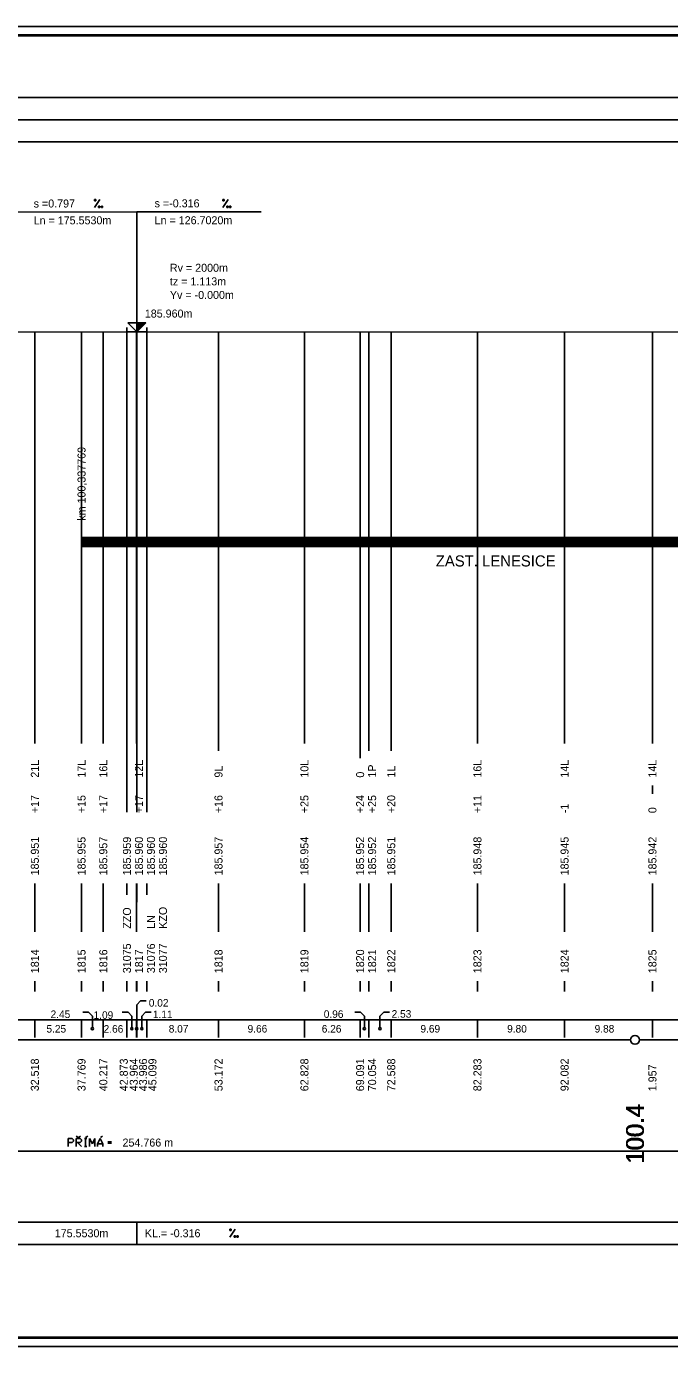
# Model space of a CAD drawing. Extents: x 0 to 10087, y -805 to 297.
# Drawn here: x 8043.1 to 8187.8, y 0 to 297 of the extents above; entities that cross this region are included whole.
import ezdxf

# ---------------------------------------------------------------- set-up
doc = ezdxf.new("R2010")
doc.units = 0
for name, color, linetype in [('CARKY_HODNOT', 7, 'Continuous'), ('KRIV1_CARA', 7, 'Continuous'), ('KRIV1_TEXT', 7, 'Continuous'), ('L_OBJEKTY_TEXT', 7, 'Continuous'), ('L_OBJEKTY_TVAR', 7, 'Continuous'), ('NIVELETA_CARA', 7, 'Continuous'), ('NIVELETA_TEXT', 7, 'Continuous'), ('RAM', 7, 'Continuous'), ('REZERVA', 7, 'Continuous'), ('STAN_CARA', 7, 'Continuous'), ('STAN_PAS', 7, 'Continuous'), ('STAN_TEXT', 7, 'Continuous'), ('TEXT', 7, 'Continuous'), ('TXT_C_BODU', 7, 'Continuous')]:
    doc.layers.add(name, color=color, linetype=linetype)

msp = doc.modelspace()

# ---------------------------------------------------------------- linework, layer by layer
at = {"layer": 'CARKY_HODNOT'}
for p, q in [((8045.04, 138.35), (8045.04, 228.25)), ((8055.54, 138.35), (8055.54, 228.28)), ((8060.43, 138.35), (8060.43, 228.29)), ((8065.75, 138.35), (8065.75, 228.3)), ((8067.93, 138.35), (8067.93, 228.3)), ((8067.97, 138.35), (8067.97, 228.3)), ((8070.2, 138.35), (8070.2, 228.3)), ((8086.34, 138.35), (8086.34, 228.29)), ((8105.66, 138.35), (8105.66, 228.27)), ((8118.18, 138.35), (8118.18, 228.26)), ((8120.11, 138.35), (8120.11, 228.26)), ((8125.18, 138.35), (8125.18, 228.25)), ((8144.57, 138.35), (8144.57, 228.24)), ((8164.16, 138.35), (8164.16, 228.22)), ((8183.91, 138.35), (8183.91, 228.21)), ((8045.04, 135.65), (8045.04, 138.35)), ((8055.54, 135.65), (8055.54, 138.35)), ((8060.43, 135.65), (8060.43, 138.35)), ((8065.75, 126.2), (8065.75, 138.35)), ((8067.93, 135.65), (8067.93, 138.35)), ((8067.97, 126.2), (8067.97, 138.35)), ((8070.2, 126.2), (8070.2, 138.35)), ((8086.34, 134), (8086.34, 138.35)), ((8105.66, 135.65), (8105.66, 138.35)), ((8118.18, 132.35), (8118.18, 138.35)), ((8120.11, 134), (8120.11, 138.35)), ((8125.18, 134), (8125.18, 138.35)), ((8144.57, 135.65), (8144.57, 138.35)), ((8164.16, 135.65), (8164.16, 138.35)), ((8183.91, 135.65), (8183.91, 138.35)), ((8065.75, 120.25), (8065.75, 126.2)), ((8067.97, 120.25), (8067.97, 126.2)), ((8070.2, 120.25), (8070.2, 126.2)), ((8183.91, 124.35), (8183.91, 126.2)), ((8045.04, 93.3), (8045.04, 104.2)), ((8055.54, 93.3), (8055.54, 104.2)), ((8060.43, 93.3), (8060.43, 104.2)), ((8065.75, 101.65), (8065.75, 104.2)), ((8067.93, 93.3), (8067.93, 104.2)), ((8067.97, 100), (8067.97, 104.2)), ((8070.2, 101.65), (8070.2, 104.2)), ((8086.34, 93.3), (8086.34, 104.2)), ((8105.66, 93.3), (8105.66, 104.2)), ((8118.18, 93.3), (8118.18, 104.2)), ((8120.11, 93.3), (8120.11, 104.2)), ((8125.18, 93.3), (8125.18, 104.2)), ((8144.57, 93.3), (8144.57, 104.2)), ((8164.16, 93.3), (8164.16, 104.2)), ((8183.91, 93.3), (8183.91, 104.2)), ((8045.04, 79.9), (8045.04, 82.2)), ((8055.54, 79.9), (8055.54, 82.2)), ((8060.43, 79.9), (8060.43, 82.2)), ((8065.75, 79.9), (8065.75, 82.2)), ((8067.93, 79.9), (8067.93, 82.2)), ((8067.97, 79.9), (8067.97, 82.2)), ((8070.2, 79.9), (8070.2, 82.2)), ((8086.34, 79.9), (8086.34, 82.2)), ((8105.66, 79.9), (8105.66, 82.2)), ((8118.18, 79.9), (8118.18, 82.2)), ((8120.11, 79.9), (8120.11, 82.2)), ((8125.18, 79.9), (8125.18, 82.2)), ((8144.57, 79.9), (8144.57, 82.2)), ((8164.16, 79.9), (8164.16, 82.2)), ((8183.91, 79.9), (8183.91, 82.2))]:
    msp.add_line(p, q, dxfattribs=at)
at = {"layer": 'KRIV1_CARA'}
msp.add_line((7811.8, 44), (8321.33, 44), dxfattribs=at)
at = {"layer": 'KRIV1_TEXT'}
for p, q in [((8052.54, 45), (8052.54, 46.8)), ((8052.54, 46.8), (8053.46, 46.8)), ((8053.44, 45.9), (8052.54, 45.9)), ((8053.76, 46.2), (8053.44, 45.9)), ((8053.46, 46.8), (8053.76, 46.49)), ((8053.76, 46.49), (8053.76, 46.2)), ((8054.83, 47.03), (8054.32, 47.37)), ((8054.34, 45), (8054.34, 46.8)), ((8054.34, 46.8), (8055.24, 46.8)), ((8055.24, 45.9), (8054.34, 45.9)), ((8054.64, 45.9), (8055.54, 45)), ((8054.83, 47.03), (8055.34, 47.37)), ((8055.24, 46.8), (8055.54, 46.51)), ((8055.54, 46.2), (8055.24, 45.9)), ((8055.54, 46.51), (8055.54, 46.2)), ((8056.18, 46.79), (8056.75, 46.79)), ((8056.18, 45), (8056.75, 45)), ((8056.46, 47.03), (8056.97, 47.37)), ((8056.46, 45), (8056.46, 46.79)), ((8057.35, 45), (8057.35, 46.79)), ((8057.35, 46.79), (8057.97, 45.6)), ((8057.97, 45.6), (8058.55, 46.79)), ((8058.55, 46.79), (8058.55, 45)), ((8059.75, 46.81), (8059.15, 45.6)), ((8059.15, 45), (8059.15, 45.6)), ((8059.15, 45.6), (8060.35, 45.6)), ((8060.35, 45.6), (8059.75, 46.81)), ((8059.77, 47.03), (8060.28, 47.37)), ((8060.35, 45.6), (8060.35, 45)), ((8061.47, 46.07), (8062.28, 46.07)), ((8061.47, 45.75), (8062.28, 45.75))]:
    msp.add_line(p, q, dxfattribs=at)
at = {"layer": 'L_OBJEKTY_TVAR'}
for p, q in [((8055.54, 180), (8055.54, 183)), ((8055.54, 182), (8246.96, 182)), ((8055.54, 181.9), (8246.96, 181.9)), ((8055.54, 181.8), (8246.96, 181.8)), ((8055.54, 181.7), (8246.96, 181.7)), ((8055.54, 181.6), (8246.96, 181.6)), ((8055.54, 181.5), (8246.96, 181.5)), ((8055.54, 181.4), (8246.96, 181.4)), ((8055.54, 181.3), (8246.96, 181.3)), ((8055.54, 181.2), (8246.96, 181.2)), ((8055.54, 181.1), (8246.96, 181.1)), ((8055.54, 181), (8246.96, 181)), ((8055.54, 180.9), (8246.96, 180.9)), ((8055.54, 180.8), (8246.96, 180.8)), ((8055.54, 180.7), (8246.96, 180.7)), ((8055.54, 180.6), (8246.96, 180.6)), ((8055.54, 180.5), (8246.96, 180.5)), ((8055.54, 180.4), (8246.96, 180.4)), ((8055.54, 180.3), (8246.96, 180.3)), ((8055.54, 180.2), (8246.96, 180.2)), ((8055.54, 180.1), (8246.96, 180.1)), ((8055.54, 180), (8246.96, 180))]:
    msp.add_line(p, q, dxfattribs=at)
at = {"layer": 'NIVELETA_CARA'}
for p, q in [((300, 281), (8321.33, 281)), ((300, 276), (8321.33, 276)), ((300, 271), (8321.33, 271)), ((8067.97, 255.3), (8039.97, 255.24)), ((8067.97, 228.3), (8067.97, 255.3)), ((8067.97, 255.3), (8095.97, 255.28)), ((8065.75, 228.3), (8065.75, 229.3)), ((8067.97, 228.3), (8065.97, 230.3)), ((8065.97, 230.3), (8069.97, 230.3)), ((8067.97, 228.3), (8067.97, 230.3)), ((8069.97, 230.3), (8067.97, 228.3)), ((8068.04, 228.37), (8068.04, 230.3)), ((8068.11, 228.43), (8068.11, 230.3)), ((8068.17, 228.5), (8068.17, 230.3)), ((8068.24, 228.57), (8068.24, 230.3)), ((8068.31, 228.63), (8068.31, 230.3)), ((8068.37, 228.7), (8068.37, 230.3)), ((8068.44, 228.77), (8068.44, 230.3)), ((8068.51, 228.83), (8068.51, 230.3)), ((8068.57, 228.9), (8068.57, 230.3)), ((8068.64, 228.97), (8068.64, 230.3)), ((8068.71, 229.03), (8068.71, 230.3)), ((8068.77, 229.1), (8068.77, 230.3)), ((8068.84, 229.17), (8068.84, 230.3)), ((8068.91, 229.23), (8068.91, 230.3)), ((8068.97, 229.3), (8068.97, 230.3)), ((8069.04, 229.37), (8069.04, 230.3)), ((8069.11, 229.43), (8069.11, 230.3)), ((8069.17, 229.5), (8069.17, 230.3)), ((8069.24, 229.57), (8069.24, 230.3)), ((8069.31, 229.63), (8069.31, 230.3)), ((8069.37, 229.7), (8069.37, 230.3)), ((8069.44, 229.77), (8069.44, 230.3)), ((8069.51, 229.83), (8069.51, 230.3)), ((8069.57, 229.9), (8069.57, 230.3)), ((8069.64, 229.97), (8069.64, 230.3)), ((8069.71, 230.03), (8069.71, 230.3)), ((8069.77, 230.1), (8069.77, 230.3)), ((8069.84, 230.17), (8069.84, 230.3)), ((8069.91, 230.23), (8069.91, 230.3)), ((8070.2, 228.3), (8070.2, 229.3)), ((7721.21, 227.61), (8065.75, 228.3)), ((8065.75, 228.3), (8067.97, 228.3)), ((8065.75, 228.3), (8066.25, 228.3)), ((8066.25, 228.3), (8066.75, 228.3)), ((8066.75, 228.3), (8067.25, 228.3)), ((8067.25, 228.3), (8067.75, 228.3)), ((8067.75, 228.3), (8067.97, 228.3)), ((8067.97, 228.3), (8070.2, 228.3)), ((8067.97, 228.3), (8068.47, 228.3)), ((8068.47, 228.3), (8068.97, 228.3)), ((8068.97, 228.3), (8069.47, 228.3)), ((8069.47, 228.3), (8069.97, 228.3)), ((8069.97, 228.3), (8070.2, 228.3)), ((8070.2, 228.3), (8321.38, 228.1)), ((500, 28), (8321.33, 28)), ((8067.97, 23), (8067.97, 28)), ((500, 23), (8321.33, 23))]:
    msp.add_line(p, q, dxfattribs=at)
at = {"layer": 'NIVELETA_TEXT'}
for p, q in [((8058.47, 256.28), (8059.66, 258.08)), ((8058.47, 258.08), (8058.47, 257.78)), ((8058.48, 258.08), (8058.47, 258.07)), ((8058.47, 257.78), (8058.77, 257.78)), ((8058.77, 258.08), (8058.48, 258.08)), ((8058.77, 257.78), (8058.77, 258.08)), ((8059.38, 256.58), (8059.38, 256.29)), ((8059.39, 256.58), (8059.38, 256.58)), ((8059.38, 256.29), (8059.68, 256.29)), ((8059.68, 256.58), (8059.39, 256.58)), ((8059.68, 256.29), (8059.68, 256.58)), ((8060, 256.58), (8060, 256.29)), ((8060.29, 256.58), (8060, 256.58)), ((8060, 256.58), (8060, 256.58)), ((8060, 256.29), (8060.29, 256.29)), ((8060.29, 256.29), (8060.29, 256.58)), ((8087.32, 256.29), (8088.51, 258.08)), ((8087.33, 258.08), (8087.33, 257.78)), ((8087.62, 258.08), (8087.33, 258.08)), ((8087.33, 258.08), (8087.33, 258.08)), ((8087.33, 257.78), (8087.62, 257.78)), ((8087.62, 257.78), (8087.62, 258.08)), ((8088.23, 256.58), (8088.23, 256.29)), ((8088.24, 256.58), (8088.23, 256.58)), ((8088.23, 256.29), (8088.53, 256.29)), ((8088.53, 256.58), (8088.24, 256.58)), ((8088.53, 256.29), (8088.53, 256.58)), ((8088.85, 256.58), (8088.85, 256.29)), ((8089.14, 256.58), (8088.85, 256.58)), ((8088.85, 256.58), (8088.85, 256.58)), ((8088.85, 256.29), (8089.14, 256.29)), ((8089.14, 256.29), (8089.14, 256.58)), ((8088.92, 24.6), (8090.11, 26.4)), ((8088.92, 26.4), (8088.92, 26.1)), ((8088.93, 26.4), (8088.92, 26.39)), ((8088.92, 26.1), (8089.22, 26.1)), ((8089.22, 26.4), (8088.93, 26.4)), ((8089.22, 26.1), (8089.22, 26.4)), ((8089.83, 24.9), (8089.83, 24.6)), ((8089.84, 24.9), (8089.83, 24.89)), ((8089.83, 24.6), (8090.13, 24.6)), ((8090.13, 24.9), (8089.84, 24.9)), ((8090.13, 24.6), (8090.13, 24.9)), ((8090.45, 24.9), (8090.45, 24.6)), ((8090.74, 24.9), (8090.45, 24.9)), ((8090.45, 24.9), (8090.45, 24.89)), ((8090.45, 24.6), (8090.74, 24.6)), ((8090.74, 24.6), (8090.74, 24.9))]:
    msp.add_line(p, q, dxfattribs=at)
at = {"layer": 'RAM'}
for p, q in [((8636.33, 297), (0, 297)), ((8634.33, 295.1), (2, 295.1)), ((8634.33, 295), (2, 295)), ((8634.33, 294.9), (2, 294.9)), ((0, 0), (8636.33, 0)), ((2, 2.1), (8634.33, 2.1)), ((2, 2), (8634.33, 2)), ((2, 1.9), (8634.33, 1.9))]:
    msp.add_line(p, q, dxfattribs=at)
at = {"layer": 'REZERVA'}
msp.add_circle((8180, 69), 1, dxfattribs=at)
at = {"layer": 'STAN_CARA'}
for p, q in [((7981, 69), (8179, 69)), ((8181, 69), (8321.33, 69))]:
    msp.add_line(p, q, dxfattribs=at)
at = {"layer": 'STAN_PAS'}
for p, q in [((8067.95, 76.9), (8068.8, 77.75)), ((8068.8, 77.75), (8070.08, 77.75)), ((8057.14, 75.2), (8055.86, 75.2)), ((8057.99, 74.35), (8057.14, 75.2)), ((8057.99, 71.75), (8057.99, 74.35)), ((8065.99, 75.2), (8064.71, 75.2)), ((8066.84, 74.35), (8065.99, 75.2)), ((8066.84, 71.75), (8066.84, 74.35)), ((8067.95, 71.75), (8067.95, 76.9)), ((8069.09, 74.35), (8069.94, 75.2)), ((8069.09, 71.75), (8069.09, 74.35)), ((8069.94, 75.2), (8071.21, 75.2)), ((8118.29, 75.2), (8117.02, 75.2)), ((8119.14, 74.35), (8118.29, 75.2)), ((8119.14, 71.75), (8119.14, 74.35)), ((8122.64, 74.35), (8123.49, 75.2)), ((8122.64, 71.75), (8122.64, 74.35)), ((8123.49, 75.2), (8124.77, 75.2)), ((300, 73.5), (8321.33, 73.5)), ((8045.04, 69.5), (8045.04, 73.5)), ((8055.54, 69.5), (8055.54, 73.5)), ((8060.43, 69.5), (8060.43, 73.5)), ((8065.75, 69.5), (8065.75, 73.5)), ((8067.93, 69.5), (8067.93, 73.5)), ((8067.97, 69.5), (8067.97, 73.5)), ((8070.2, 69.5), (8070.2, 73.5)), ((8086.34, 69.5), (8086.34, 73.5)), ((8105.66, 69.5), (8105.66, 73.5)), ((8118.18, 69.5), (8118.18, 73.5)), ((8120.11, 69.5), (8120.11, 73.5)), ((8125.18, 69.5), (8125.18, 73.5)), ((8144.57, 69.5), (8144.57, 73.5)), ((8164.16, 69.5), (8164.16, 73.5)), ((8183.91, 69.5), (8183.91, 73.5))]:
    msp.add_line(p, q, dxfattribs=at)
for centre in [(8057.99, 71.5), (8066.84, 71.5), (8067.95, 71.5), (8069.09, 71.5), (8119.14, 71.5), (8122.64, 71.5)]:
    msp.add_circle(centre, 0.25, dxfattribs=at)

# ---------------------------------------------------------------- texts
at = {"layer": 'KRIV1_TEXT'}
msp.add_text(' 254.766 m', height=1.8, dxfattribs=at).set_placement((8064.09, 45))
at = {"layer": 'L_OBJEKTY_TEXT'}
msp.add_text('km 100,337769', height=1.8, rotation=90, dxfattribs=at).set_placement((8056.44, 185.8))
msp.add_text('ZAST. LENESICE', height=2.5, dxfattribs=at).set_placement((8135.2, 175.5))
at = {"layer": 'NIVELETA_TEXT'}
for s, rotation, p in [('s =0.797', 0.1142, (8044.77, 256.25)), ('s =-0.316', 359.9548, (8071.97, 256.3)), ('Ln = 175.5530m', 0.1142, (8044.77, 252.45)), ('Ln = 126.7020m', 359.9548, (8071.97, 252.5))]:
    msp.add_text(s, height=1.8, rotation=rotation, dxfattribs=at).set_placement(p)
for s, p in [('Rv = 2000m', (8075.41, 241.8)), ('tz = 1.113m', (8075.41, 238.74)), ('Yv = -0.000m', (8075.41, 235.68)), ('185.960m', (8069.77, 231.5)), ('175.5530m', (8049.52, 24.6)), ('KL.= -0.316', (8069.77, 24.6))]:
    msp.add_text(s, height=1.8, dxfattribs=at).set_placement(p)
at = {"layer": 'STAN_TEXT'}
for s, p in [('0.02', (8070.67, 76.48)), ('2.45', (8048.58, 73.92)), ('1.09', (8058.25, 73.73)), ('1.11', (8071.59, 73.89)), ('0.96', (8110.01, 73.95)), ('2.53', (8125.27, 73.99)), ('5.25', (8047.65, 70.64)), ('2.66', (8060.51, 70.62)), ('8.07', (8075.15, 70.65)), ('9.66', (8092.88, 70.65)), ('6.26', (8109.56, 70.64)), ('9.69', (8131.75, 70.65)), ('9.80', (8151.25, 70.65)), ('9.88', (8170.92, 70.65))]:
    msp.add_text(s, height=1.7, dxfattribs=at).set_placement(p)
for s, height, p in [('32.518', 1.8, (8045.94, 57.45)), ('37.769', 1.8, (8056.44, 57.45)), ('40.217', 1.8, (8061.33, 57.45)), ('42.873', 1.8, (8065.94, 57.45)), ('43.964', 1.8, (8068.18, 57.45)), ('43.986', 1.8, (8070.26, 57.45)), ('45.099', 1.8, (8072.38, 57.45)), ('53.172', 1.8, (8087.24, 57.45)), ('62.828', 1.8, (8106.56, 57.45)), ('69.091', 1.8, (8119.08, 57.45)), ('70.054', 1.8, (8121.78, 57.45)), ('72.588', 1.8, (8126.08, 57.45)), ('82.283', 1.8, (8145.47, 57.45)), ('92.082', 1.8, (8165.06, 57.45)), ('1.957', 1.8, (8184.82, 57.45)), ('   100.4', 4, (8182, 36.84)), ('   100.4', 4, (8182, 36.74)), ('   100.4', 4, (8182, 36.64))]:
    msp.add_text(s, height=height, rotation=90, dxfattribs=at).set_placement(p)
at = {"layer": 'TEXT'}
for s, p in [('21L', (8045.94, 128)), ('17L', (8056.44, 128)), ('16L', (8061.33, 128)), ('12L', (8069.35, 128)), ('10L', (8106.56, 128)), ('1P', (8121.78, 128)), ('16L', (8145.47, 128)), ('14L', (8165.06, 128)), ('14L', (8184.82, 128)), ('9L', (8087.24, 128)), ('0', (8119.08, 128)), ('1L', (8126.08, 128)), ('+17', (8045.94, 120)), ('+15', (8056.44, 120)), ('+17', (8061.33, 120)), ('+17', (8069.35, 120)), ('+16', (8087.24, 120)), ('+25', (8106.56, 120)), ('+24', (8119.08, 120)), ('+25', (8121.78, 120)), ('+20', (8126.08, 120)), ('+11', (8145.47, 120)), ('-1', (8165.06, 120)), ('0', (8184.82, 120)), ('185.951', (8045.94, 106)), ('185.955', (8056.44, 106)), ('185.957', (8061.33, 106)), ('185.959', (8066.65, 106)), ('185.960', (8069.35, 106)), ('185.960', (8072.05, 106)), ('185.960', (8074.75, 106)), ('185.957', (8087.24, 106)), ('185.954', (8106.56, 106)), ('185.952', (8119.08, 106)), ('185.952', (8121.78, 106)), ('185.951', (8126.08, 106)), ('185.948', (8145.47, 106)), ('185.945', (8165.06, 106)), ('185.942', (8184.82, 106)), ('ZZO', (8066.65, 94)), ('KZO', (8074.75, 94)), ('LN', (8072.05, 94))]:
    msp.add_text(s, height=1.8, rotation=90, dxfattribs=at).set_placement(p)
at = {"layer": 'TXT_C_BODU'}
for s, p in [('1814', (8045.94, 84)), ('1815', (8056.44, 84)), ('1816', (8061.33, 84)), ('31075', (8066.65, 84)), ('1817', (8069.35, 84)), ('31076', (8072.05, 84)), ('31077', (8074.75, 84)), ('1818', (8087.24, 84)), ('1819', (8106.56, 84)), ('1820', (8119.08, 84)), ('1821', (8121.78, 84)), ('1822', (8126.08, 84)), ('1823', (8145.47, 84)), ('1824', (8165.06, 84)), ('1825', (8184.82, 84))]:
    msp.add_text(s, height=1.8, rotation=90, dxfattribs=at).set_placement(p)

doc.saveas('drawing.dxf')
